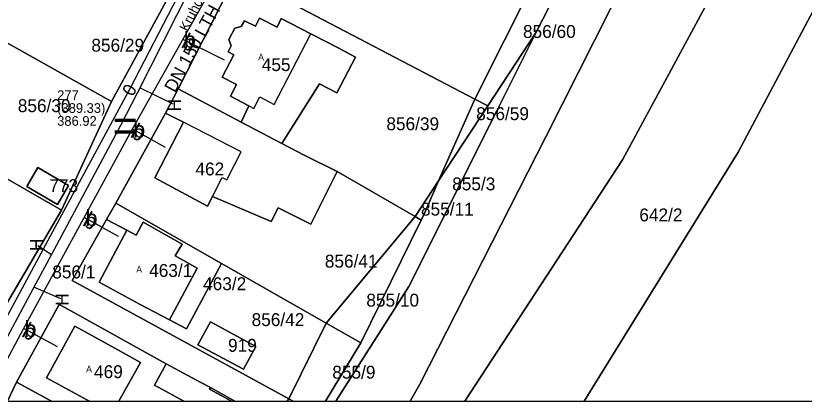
# Model space of a CAD drawing. Extents: x -564940 to -564406, y -1066466 to -1066072.
# Drawn here: x -564670.5 to -564548.1, y -1066465.6 to -1066405.8 of the extents above; entities that cross this region are included whole.
import ezdxf

# ---------------------------------------------------------------- set-up
doc = ezdxf.new("R2010")
doc.units = 0
for name, color, linetype in [('ft_g_5211', 7, 'Continuous'), ('ft_g_5411', 7, 'Continuous'), ('ft_g_6031', 7, 'Continuous'), ('ft_g_6040', 7, 'Continuous'), ('ft_g_6101', 7, 'Continuous'), ('ft_g_6101_ft_g_6101_da_6108_gtc_da_6108', 7, 'Continuous'), ('ft_g_6220', 7, 'Continuous'), ('ft_g_gps_soupe_pri', 7, 'Continuous'), ('ft_g_stoka', 7, 'Continuous'), ('ft_g_stoka_ft_g_stoka_da_popis_gtc_da_6004', 7, 'Continuous'), ('ft_g_vrad', 7, 'Continuous'), ('ft_g_vrad_ft_g_vrad_da_popis_gtc_da_5091', 7, 'Continuous'), ('ft_parcela_polygon', 7, 'Continuous'), ('ft_parcela_text', 7, 'Continuous'), ('ft_stavebni_objekt_bod', 7, 'Continuous'), ('ft_stavebni_objekt_polygon', 7, 'Continuous')]:
    doc.layers.add(name, color=color, linetype=linetype)

msp = doc.modelspace()

# ---------------------------------------------------------------- linework, layer by layer
at = {"layer": 'ft_g_5211'}
msp.add_line((-564644.55, -1066409.45), (-564638.13, -1066412.67), dxfattribs=at)
for points in [[(-564652.37, -1066423.4), (-564652.2, -1066423.49), (-564647.28, -1066426.19)], [(-564659.84, -1066437.08), (-564659.75, -1066437.13), (-564659.6, -1066437.21), (-564654.57, -1066440.03)], [(-564669.24, -1066454.32), (-564669.07, -1066454.41), (-564664.04, -1066457.12)]]:
    msp.add_lwpolyline(points, dxfattribs=at)
at = {"layer": 'ft_g_6040'}
for p, q in [((-564646.06, -1066419.55), (-564651.23, -1066417.02)), ((-564667.04, -1066441.49), (-564664.94, -1066442.86)), ((-564663.49, -1066449.73), (-564667.65, -1066447.91))]:
    msp.add_line(p, q, dxfattribs=at)
at = {"layer": 'ft_g_stoka'}
for points in [[(-564553.41, -1066163.16), (-564553.48, -1066166.31), (-564548.89, -1066191.56), (-564549.63, -1066201.37), (-564551.36, -1066210.53), (-564553.55, -1066218.37), (-564556.52, -1066226.67), (-564558.83, -1066231.76), (-564567.86, -1066249.71), (-564582.71, -1066279.41), (-564586.53, -1066287.4), (-564596.46, -1066308.15), (-564604.5, -1066323.01), (-564613.83, -1066341.28), (-564619.05, -1066351.65), (-564629.23, -1066370.83), (-564638.15, -1066388.86), (-564652.7, -1066417.07), (-564664.74, -1066439.37), (-564677.25, -1066462.42), (-564679.03, -1066465.63)], [(-564633.79, -1066382.77), (-564637.59, -1066390.24), (-564645.51, -1066405.79), (-564651.64, -1066417.82), (-564654.2, -1066422.86)], [(-564654.2, -1066422.86), (-564664.94, -1066442.85), (-564667.42, -1066447.47), (-564675.37, -1066462.28), (-564677.17, -1066465.63)]]:
    msp.add_lwpolyline(points, dxfattribs=at)
at = {"layer": 'ft_g_vrad'}
msp.add_lwpolyline([(-564573.05, -1066269.82), (-564574.29, -1066272.32), (-564577.91, -1066279.06), (-564602.05, -1066327.68), (-564604.48, -1066332.96), (-564632.28, -1066386.02), (-564638.67, -1066398.97), (-564652.45, -1066423.53), (-564669.32, -1066454.46), (-564675.34, -1066465.63)], dxfattribs=at)
at = {"layer": 'ft_parcela_polygon'}
for p, q in [((-564671.75, -1066465.63), (-564664.94, -1066465.63)), ((-564664.94, -1066465.63), (-564659.03, -1066465.63)), ((-564659.03, -1066465.63), (-564654.46, -1066465.63)), ((-564654.46, -1066465.63), (-564644.41, -1066465.63)), ((-564644.41, -1066465.63), (-564637, -1066465.63)), ((-564637, -1066465.63), (-564636.48, -1066465.63)), ((-564636.48, -1066465.63), (-564628.33, -1066465.63)), ((-564628.33, -1066465.63), (-564627.44, -1066465.63)), ((-564627.44, -1066465.63), (-564622.39, -1066465.63)), ((-564622.39, -1066465.63), (-564620.81, -1066465.63)), ((-564620.81, -1066465.63), (-564609.27, -1066465.63)), ((-564609.27, -1066465.63), (-564600.77, -1066465.63)), ((-564600.77, -1066465.63), (-564582.26, -1066465.63)), ((-564582.26, -1066465.63), (-564541.21, -1066465.63))]:
    msp.add_line(p, q, dxfattribs=at)
for points in [[(-564506.93, -1066072.02), (-564500.76, -1066095.62), (-564490.54, -1066131.29), (-564485.08, -1066150.07), (-564474.86, -1066195.24), (-564468.44, -1066228.77), (-564474.86, -1066248.97), (-564479.58, -1066256.49), (-564510.51, -1066292.89), (-564526.05, -1066309.43), (-564540.77, -1066329.78), (-564548.05, -1066345), (-564588.23, -1066424.58), (-564607.75, -1066462.97), (-564609.27, -1066465.63)], [(-564609.27, -1066465.63), (-564607.75, -1066462.97), (-564588.23, -1066424.58), (-564548.05, -1066345), (-564540.77, -1066329.78), (-564526.05, -1066309.43), (-564510.51, -1066292.89), (-564479.58, -1066256.49), (-564474.86, -1066248.97), (-564468.44, -1066228.77), (-564474.86, -1066195.24), (-564485.08, -1066150.07), (-564490.54, -1066131.29), (-564500.76, -1066095.62), (-564506.93, -1066072.02)], [(-564600.77, -1066465.63), (-564576.34, -1066428.17), (-564561.1, -1066399.98), (-564552.57, -1066377.06), (-564544.46, -1066346.76), (-564506.9, -1066296.8), (-564477.41, -1066257.73), (-564467.26, -1066239.44), (-564459.83, -1066220.33), (-564457.63, -1066204.67), (-564458.61, -1066193.4), (-564464.89, -1066162.6), (-564473.06, -1066136.49), (-564496.21, -1066076.34), (-564497.57, -1066072.02)], [(-564497.57, -1066072.02), (-564496.21, -1066076.34), (-564473.06, -1066136.49), (-564464.89, -1066162.6), (-564458.61, -1066193.4), (-564457.63, -1066204.67), (-564459.83, -1066220.33), (-564467.26, -1066239.44), (-564477.41, -1066257.73), (-564506.9, -1066296.8), (-564544.46, -1066346.76), (-564552.57, -1066377.06), (-564561.1, -1066399.98), (-564576.34, -1066428.17), (-564600.77, -1066465.63)], [(-564428.01, -1066072.02), (-564431.34, -1066090.43), (-564438.01, -1066109.82), (-564446.27, -1066122.38), (-564434.59, -1066131.44), (-564440.14, -1066155.47), (-564448.27, -1066160.12), (-564443.92, -1066174.88), (-564442.56, -1066204.14), (-564447.75, -1066227.88), (-564462.14, -1066258.44), (-564480.38, -1066282.47), (-564512.56, -1066319.56), (-564528.58, -1066341.81), (-564532.13, -1066347.45), (-564535.25, -1066353.98), (-564543.55, -1066398.93), (-564558.38, -1066426.97), (-564582.26, -1066465.63)], [(-564582.26, -1066465.63), (-564558.38, -1066426.97), (-564543.55, -1066398.93), (-564535.25, -1066353.98), (-564532.13, -1066347.45), (-564528.58, -1066341.81), (-564512.56, -1066319.56), (-564480.38, -1066282.47), (-564462.14, -1066258.44), (-564447.75, -1066227.88), (-564442.56, -1066204.14), (-564443.92, -1066174.88), (-564448.27, -1066160.12), (-564456.43, -1066140.31), (-564460.8, -1066129.7), (-564472.45, -1066131.84), (-564488.63, -1066076.11), (-564489.48, -1066072.02)], [(-564519.39, -1066285.88), (-564526.09, -1066292.91), (-564547.92, -1066324.79), (-564551.67, -1066325.09), (-564555.65, -1066325.14), (-564559.33, -1066331.43), (-564556.55, -1066333.83), (-564553.56, -1066336.41), (-564579.89, -1066388.86), (-564586.69, -1066402.39), (-564589.7, -1066408.39), (-564595.81, -1066420.56), (-564609.5, -1066447.82), (-564620.81, -1066465.63)], [(-564628.33, -1066465.63), (-564628.12, -1066465.26), (-564661.74, -1066446.92), (-564656.38, -1066437.43), (-564654.96, -1066434.92), (-564647.21, -1066420.91), (-564645.29, -1066417.18), (-564636.21, -1066399.34), (-564626.67, -1066381.79), (-564621.16, -1066371.09), (-564619.75, -1066368.35), (-564616.93, -1066362.92), (-564610.68, -1066350.52), (-564606.31, -1066341.84), (-564601.53, -1066332.64), (-564594.17, -1066318.35), (-564601.68, -1066315.73), (-564632.08, -1066373.21), (-564646.54, -1066402.48), (-564655.62, -1066419.11), (-564663.36, -1066435.96), (-564680.82, -1066465.63)], [(-564620.81, -1066465.63), (-564609.5, -1066447.82), (-564595.81, -1066420.56), (-564589.7, -1066408.39), (-564597.21, -1066419.82), (-564604.85, -1066431.45), (-564606.96, -1066436.22), (-564607.54, -1066437.53), (-564616.91, -1066456.57), (-564622.39, -1066465.63)], [(-564680.82, -1066465.63), (-564663.36, -1066435.96), (-564697.04, -1066416.62), (-564715.26, -1066446.5), (-564685.61, -1066465.63)], [(-564671.75, -1066465.63), (-564670.33, -1066462.7), (-564663.75, -1066450.61), (-564662.84, -1066451.11), (-564647.12, -1066459.81), (-564641.74, -1066462.71), (-564640.27, -1066463.52), (-564636.48, -1066465.63)], [(-564644.41, -1066465.63), (-564648.93, -1066463.14), (-564647.12, -1066459.81), (-564662.84, -1066451.11), (-564663.75, -1066450.61), (-564670.33, -1066462.7), (-564664.94, -1066465.63)], [(-564622.39, -1066465.63), (-564616.91, -1066456.57), (-564622.3, -1066453.5), (-564628.12, -1066465.26), (-564627.44, -1066465.63)], [(-564659.03, -1066465.63), (-564659.45, -1066465.4), (-564665.68, -1066461.98), (-564661.3, -1066454), (-564655.08, -1066457.42), (-564651.13, -1066459.61), (-564654.46, -1066465.63)], [(-564654.46, -1066465.63), (-564651.13, -1066459.61), (-564655.08, -1066457.42), (-564661.3, -1066454), (-564665.68, -1066461.98), (-564659.45, -1066465.4), (-564659.03, -1066465.63)], [(-564637, -1066465.63), (-564640.41, -1066463.74), (-564640.27, -1066463.52), (-564641.74, -1066462.71), (-564647.12, -1066459.81), (-564648.93, -1066463.14), (-564644.41, -1066465.63)], [(-564664.94, -1066465.63), (-564670.33, -1066462.7), (-564671.75, -1066465.63)], [(-564636.48, -1066465.63), (-564640.27, -1066463.52), (-564640.41, -1066463.74), (-564637, -1066465.63)], [(-564627.44, -1066465.63), (-564628.12, -1066465.26), (-564628.33, -1066465.63)]]:
    msp.add_lwpolyline(points, dxfattribs=at)
for points in [[(-564599.25, -1066418.75), (-564590.13, -1066400.62), (-564613.23, -1066388.71), (-564626.67, -1066381.79), (-564636.21, -1066399.34)], [(-564655.62, -1066419.11), (-564646.54, -1066402.48), (-564661.73, -1066394.69), (-564679.74, -1066385.3), (-564681.08, -1066387.68), (-564673.46, -1066391.66), (-564672.57, -1066392.13), (-564673.96, -1066394.79), (-564674.85, -1066394.32), (-564678.14, -1066400.61), (-564685.76, -1066396.63), (-564688.04, -1066401.15), (-564685.06, -1066402.78), (-564677.51, -1066406.89)], [(-564608.49, -1066436.98), (-564604.85, -1066431.45), (-564599.25, -1066418.75), (-564636.21, -1066399.34), (-564645.29, -1066417.18), (-564635.5, -1066422.32), (-564634.3, -1066419.81), (-564637.15, -1066418.32), (-564636.2, -1066416.5), (-564638.42, -1066415.34), (-564636.62, -1066411.87), (-564637.51, -1066411.4), (-564637.04, -1066410.51), (-564637.43, -1066409.52), (-564636.5, -1066407.73), (-564635.47, -1066407.48), (-564635, -1066406.59), (-564633.29, -1066407.43), (-564632.64, -1066406.18), (-564629.92, -1066407.59), (-564629.27, -1066406.23), (-564624.68, -1066408.62), (-564620.45, -1066410.82), (-564617.75, -1066412.23), (-564620.65, -1066417.8), (-564623.35, -1066416.39), (-564629.19, -1066425.64), (-564625.72, -1066427.46), (-564620.62, -1066429.99)], [(-564589.7, -1066408.39), (-564586.69, -1066402.39), (-564590.13, -1066400.62), (-564599.25, -1066418.75), (-564597.21, -1066419.82)], [(-564697.04, -1066416.62), (-564663.36, -1066435.96), (-564655.62, -1066419.11), (-564677.51, -1066406.89), (-564679.66, -1066410.84), (-564680.98, -1066410.13), (-564683.23, -1066414.25), (-564684.54, -1066413.53), (-564685.79, -1066415.82), (-564693.87, -1066411.41)], [(-564634.3, -1066419.81), (-564635.5, -1066422.32), (-564629.19, -1066425.64), (-564623.35, -1066416.39), (-564620.65, -1066417.8), (-564617.75, -1066412.23), (-564620.45, -1066410.82), (-564624.68, -1066408.62), (-564629.27, -1066406.23), (-564629.92, -1066407.59), (-564632.64, -1066406.18), (-564633.29, -1066407.43), (-564635, -1066406.59), (-564635.47, -1066407.48), (-564636.5, -1066407.73), (-564637.43, -1066409.52), (-564637.04, -1066410.51), (-564637.51, -1066411.4), (-564636.62, -1066411.87), (-564638.42, -1066415.34), (-564636.2, -1066416.5), (-564637.15, -1066418.32)], [(-564647.21, -1066420.91), (-564644.45, -1066422.33), (-564648.89, -1066430.96), (-564640.71, -1066435.38), (-564639.93, -1066433.87), (-564630.84, -1066437.76), (-564629.77, -1066435.61), (-564624.67, -1066438.14), (-564620.62, -1066429.99), (-564625.72, -1066427.46), (-564629.19, -1066425.64), (-564635.5, -1066422.32), (-564645.29, -1066417.18)], [(-564604.85, -1066431.45), (-564597.21, -1066419.82), (-564599.25, -1066418.75)], [(-564622.3, -1066453.5), (-564608.49, -1066436.98), (-564620.62, -1066429.99), (-564624.67, -1066438.14), (-564629.77, -1066435.61), (-564630.84, -1066437.76), (-564639.93, -1066433.87), (-564640.71, -1066435.38), (-564648.89, -1066430.96), (-564644.45, -1066422.33), (-564647.21, -1066420.91), (-564654.96, -1066434.92), (-564638.53, -1066444.26)], [(-564668.77, -1066432.32), (-564663.98, -1066435.08), (-564662.27, -1066432.14), (-564667.04, -1066429.35)], [(-564667.04, -1066429.35), (-564662.27, -1066432.14), (-564663.98, -1066435.08), (-564668.77, -1066432.32)], [(-564607.54, -1066437.53), (-564606.96, -1066436.22), (-564604.85, -1066431.45), (-564608.49, -1066436.98)], [(-564643.99, -1066454.38), (-564638.53, -1066444.26), (-564654.96, -1066434.92), (-564656.38, -1066437.43), (-564653.24, -1066439.1), (-564651.76, -1066439.88), (-564650.68, -1066437.85), (-564644.63, -1066441.26), (-564645.73, -1066443.09), (-564642.3, -1066444.99), (-564646.6, -1066452.98)], [(-564628.12, -1066465.26), (-564622.3, -1066453.5), (-564638.53, -1066444.26), (-564643.99, -1066454.38), (-564646.6, -1066452.98), (-564651.28, -1066450.55), (-564657.5, -1066447.14), (-564653.24, -1066439.1), (-564656.38, -1066437.43), (-564661.74, -1066446.92)], [(-564616.91, -1066456.57), (-564607.54, -1066437.53), (-564608.49, -1066436.98), (-564622.3, -1066453.5)], [(-564642.3, -1066444.99), (-564645.73, -1066443.09), (-564644.63, -1066441.26), (-564650.68, -1066437.85), (-564651.76, -1066439.88), (-564653.24, -1066439.1), (-564657.5, -1066447.14), (-564651.28, -1066450.55), (-564646.6, -1066452.98)], [(-564640.27, -1066453.31), (-564633.2, -1066457.12), (-564635.11, -1066460.68), (-564642.19, -1066456.86)], [(-564642.19, -1066456.86), (-564635.11, -1066460.68), (-564633.2, -1066457.12), (-564640.27, -1066453.31)]]:
    msp.add_lwpolyline(points, close=True, dxfattribs=at)
at = {"layer": 'ft_stavebni_objekt_polygon'}
msp.add_line((-564659.03, -1066465.63), (-564654.46, -1066465.63), dxfattribs=at)
for points in [[(-564632.61, -1066418.42), (-564630.38, -1066419.58), (-564624.68, -1066408.62), (-564629.27, -1066406.23), (-564629.92, -1066407.59), (-564632.64, -1066406.18), (-564633.29, -1066407.43), (-564635, -1066406.59), (-564635.47, -1066407.48), (-564636.5, -1066407.73), (-564637.43, -1066409.52), (-564637.04, -1066410.51), (-564637.51, -1066411.4), (-564636.62, -1066411.87), (-564638.42, -1066415.34), (-564636.2, -1066416.5), (-564637.15, -1066418.32), (-564634.3, -1066419.81), (-564633.54, -1066420.2)], [(-564644.45, -1066422.33), (-564648.89, -1066430.96), (-564640.71, -1066435.38), (-564639.93, -1066433.87), (-564638.42, -1066430.94), (-564637.71, -1066431.3), (-564635.47, -1066426.94)], [(-564646.6, -1066452.98), (-564642.3, -1066444.99), (-564645.73, -1066443.09), (-564644.63, -1066441.26), (-564650.68, -1066437.85), (-564651.76, -1066439.88), (-564653.24, -1066439.1), (-564657.5, -1066447.14), (-564651.28, -1066450.55)]]:
    msp.add_lwpolyline(points, close=True, dxfattribs=at)
msp.add_lwpolyline([(-564654.46, -1066465.63), (-564651.13, -1066459.61), (-564655.08, -1066457.42), (-564661.3, -1066454), (-564665.68, -1066461.98), (-564659.45, -1066465.4), (-564659.03, -1066465.63)], dxfattribs=at)

# ---------------------------------------------------------------- texts
at = {"layer": 'ft_g_5411'}
for rotation, p in [(333.3691, (-564644.95, -1066410.65)), (331.2142, (-564652.84, -1066424.56)), (330.7895, (-564660.25, -1066438.28)), (331.7002, (-564669.7, -1066455.49))]:
    msp.add_text('b', height=2.5, rotation=rotation, dxfattribs=at).set_placement(p)
at = {"layer": 'ft_g_6031'}
msp.add_text('0', height=2, rotation=62.5603, dxfattribs=at).set_placement((-564652.28, -1066418.45))
at = {"layer": 'ft_g_6101'}
msp.add_text('=', height=5, dxfattribs=at).set_placement((-564655.45, -1066425.36))
at = {"layer": 'ft_g_6101_ft_g_6101_da_6108_gtc_da_6108'}
for s, p in [('277', (-564664.04, -1066418.89)), ('(389.33)', (-564664.04, -1066420.89)), ('386.92', (-564664.04, -1066422.89))]:
    msp.add_text(s, height=1.5, dxfattribs=at).set_placement(p)
at = {"layer": 'ft_g_6220'}
for p in [(-564644.83, -1066420.66), (-564666.25, -1066442.35), (-564662.26, -1066450.83)]:
    msp.add_text('H', height=2, rotation=90, dxfattribs=at).set_placement(p)
at = {"layer": 'ft_g_gps_soupe_pri'}
for p in [(-564644.39, -1066410.8), (-564652.24, -1066424.74), (-564659.64, -1066438.46), (-564669.11, -1066455.66)]:
    msp.add_text('b', height=2.5, dxfattribs=at).set_placement(p)
at = {"layer": 'ft_g_stoka_ft_g_stoka_da_popis_gtc_da_6004'}
msp.add_text('Kruhové 250 PVC', height=1.5, rotation=63.018, dxfattribs=at).set_placement((-564643.82, -1066408.36))
at = {"layer": 'ft_g_vrad_ft_g_vrad_da_popis_gtc_da_5091'}
msp.add_text('DN 150 LTH', height=2, rotation=61.4032, dxfattribs=at).set_placement((-564645.77, -1066417.88))
at = {"layer": 'ft_parcela_text'}
for s, p in [('856/60', (-564591.76, -1066409.26)), ('856/29', (-564658.73, -1066411.39)), ('455', (-564632.29, -1066414.4)), ('856/30', (-564670.15, -1066420.77)), ('856/59', (-564599.02, -1066422.01)), ('856/39', (-564612.96, -1066423.58)), ('462', (-564642.59, -1066430.59)), ('773', (-564665.26, -1066433.18)), ('855/3', (-564602.75, -1066432.91)), ('855/11', (-564607.59, -1066436.83)), ('642/2', (-564573.71, -1066437.72)), ('856/41', (-564622.51, -1066444.9)), ('856/1', (-564664.8, -1066446.57)), ('463/1', (-564649.77, -1066446.34)), ('463/2', (-564641.4, -1066448.4)), ('855/10', (-564616.07, -1066450.95)), ('856/42', (-564633.87, -1066453.97)), ('919', (-564637.53, -1066457.96)), ('469', (-564658.32, -1066462.05)), ('855/9', (-564621.35, -1066462.13))]:
    msp.add_text(s, height=2, dxfattribs=at).set_placement(p)
at = {"layer": 'ft_stavebni_objekt_bod'}
for p in [(-564632.85, -1066412.71), (-564651.77, -1066445.65), (-564659.54, -1066461.13)]:
    msp.add_text('A', height=1, dxfattribs=at).set_placement(p)

doc.saveas('drawing.dxf')
